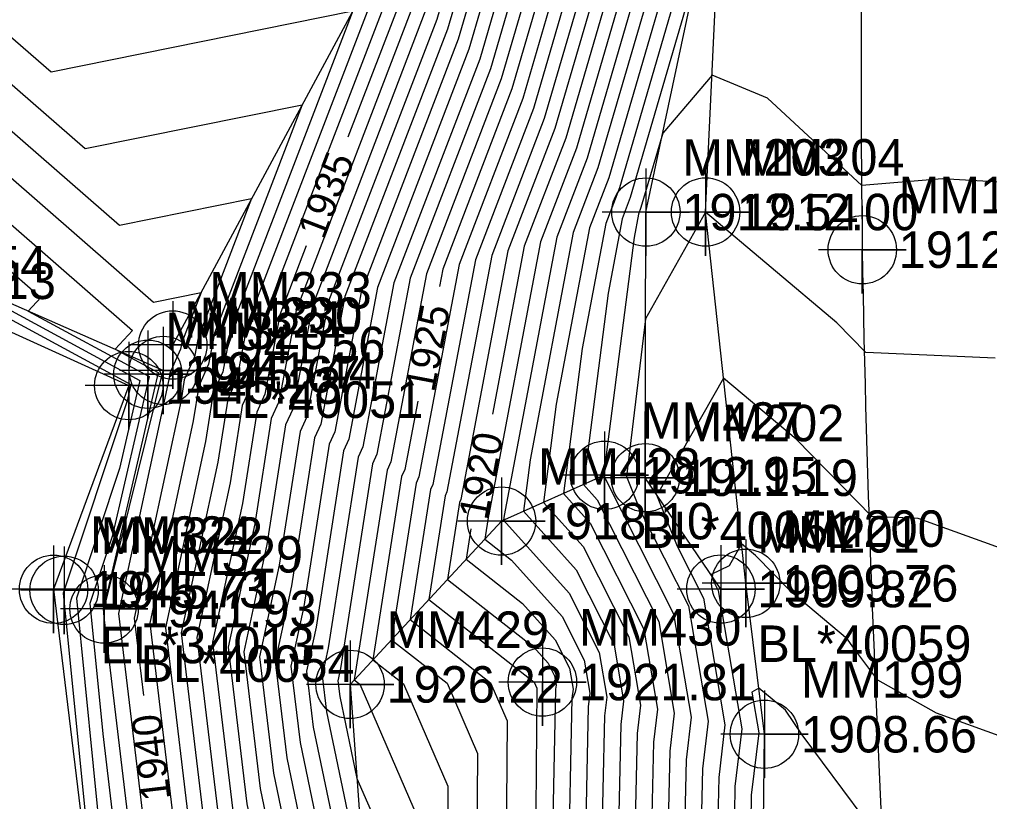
# Model space of a CAD drawing. Extents: x 1004378 to 1005103, y 553854 to 554288.
# Drawn here: x 1004943.2 to 1005009.8, y 554065.8 to 554119.4 of the extents above; entities that cross this region are included whole.
import ezdxf

# ---------------------------------------------------------------- set-up
doc = ezdxf.new("R2010")
doc.units = 0
for name, color, linetype in [('DTM Contours Major', 7, 'Continuous'), ('DTM Contours Major Text', 7, 'Continuous'), ('DTM Contours Minor', 7, 'Continuous'), ('Exist Building Cogo Elevation', 7, 'Continuous'), ('Exist Building Cogo Number', 7, 'Continuous'), ('Exist Building Cogo Point CELL', 7, 'Continuous'), ('Exist DTM Breakline', 7, 'Continuous'), ('Exist DTM Breakline Cogo Comment', 7, 'Continuous'), ('Exist DTM Breakline Cogo Elevation', 7, 'Continuous'), ('Exist DTM Breakline Cogo Number', 7, 'Continuous'), ('Exist DTM Breakline Cogo Point CELL', 7, 'Continuous'), ('Exist DTM Regular Point CELL', 7, 'Continuous'), ('Exist DTM Regular Point Cogo Elevation', 7, 'Continuous'), ('Exist DTM Regular Point Cogo Number', 7, 'Continuous'), ('Exist Roads EOP', 7, 'Continuous'), ('Exist Roads EOP Cogo Elevation', 7, 'Continuous'), ('Exist Roads EOP Cogo Number', 7, 'Continuous'), ('Exist Roads EOP Cogo Point CELL', 7, 'Continuous')]:
    doc.layers.add(name, color=color, linetype=linetype)

msp = doc.modelspace()

# ---------------------------------------------------------------- linework, layer by layer
at = {"layer": 'DTM Contours Major'}
for points in [[(1004988.055, 554197.353), (1004983.519, 554189.087), (1004981.07, 554183.147), (1004980.472, 554180.378), (1004981.231, 554169.159), (1004982.126, 554161.833), (1004982.368, 554159.624), (1004982.603, 554156.477), (1004979.182, 554142.834), (1004980.705, 554127.374), (1004976.99, 554114.65), (1004972.242, 554102.28), (1004972.017, 554101.096)], [(1004997.264, 554188.393), (1004994.509, 554183.373), (1004992.338, 554178.108), (1004990.326, 554169.606), (1004989.594, 554168.865), (1004990.186, 554164.023), (1004990.595, 554160.288), (1004990.667, 554159.321), (1004985.088, 554137.073), (1004985.877, 554129.065), (1004980.677, 554111.255), (1004977.834, 554103.85), (1004975.652, 554092.328)], [(1004974.291, 554156.941), (1004974.539, 554153.633), (1004973.275, 554148.595), (1004975.533, 554125.683), (1004973.303, 554118.045), (1004966.649, 554100.709), (1004964.833, 554091.127), (1004964.446, 554090.268), (1004962.705, 554079.148), (1004961.826, 554075.049), (1004962.449, 554069.829), (1004964.566, 554059.674), (1004964.614, 554059.515)], [(1004919.499, 554152.916), (1004917.744, 554143.914), (1004919.151, 554146.169), (1004918.574, 554141.908), (1004920.21, 554140.992), (1004926.611, 554134.921), (1004928.068, 554135.961), (1004934.459, 554132.981), (1004936.344, 554131.771), (1004937.836, 554132.01), (1004938.33, 554131.579), (1004939.667, 554131.849), (1004957.042, 554136.349), (1004968.89, 554138.926), (1004970.361, 554123.992), (1004969.616, 554121.44), (1004965.738, 554111.337)], [(1004915.782, 554139.515), (1004913.904, 554129.888), (1004921.295, 554123.861), (1004927.208, 554119.035), (1004933.185, 554119.992), (1004950.058, 554105.284), (1004959.128, 554107.116), (1004955.463, 554097.569), (1004955.218, 554096.276), (1004954.505, 554094.696), (1004954.285, 554093.293), (1004951.079, 554078.342), (1004951.712, 554073.035)], [(1005000.387, 554132.231), (1004993.714, 554134.749), (1004991.768, 554134.399), (1004990.994, 554131.312), (1004991.049, 554130.756), (1004984.364, 554107.86), (1004983.427, 554105.42), (1004981.8, 554096.829), (1004980.532, 554086.898), (1004982.359, 554084.869), (1004986.035, 554077.591), (1004986.969, 554072.114), (1004986.697, 554069.843), (1004986.544, 554062.802), (1004985.079, 554049.563), (1004984.328, 554046.826)], [(1004912.064, 554126.115), (1004911.158, 554121.47), (1004914.724, 554118.563), (1004927.833, 554107.862), (1004928.535, 554107.974), (1004932.097, 554104.869), (1004931.879, 554104.636), (1004950.839, 554094.361), (1004950.581, 554093.249), (1004946.204, 554080.072), (1004948.75, 554054.444), (1004948.799, 554054.036), (1004948.807, 554053.997), (1004948.82, 554053.955), (1004947.217, 554049.061)], [(1004962.871, 554103.868), (1004961.056, 554099.139), (1004960.026, 554093.701), (1004959.475, 554092.482), (1004958.495, 554086.221), (1004956.453, 554076.695), (1004957.899, 554064.565), (1004959.313, 554057.782), (1004961.493, 554050.599), (1004960.632, 554047.97), (1004960.758, 554033.678), (1004963.076, 554011.188), (1004962.949, 554005.526)], [(1004970.528, 554093.236), (1004969.641, 554088.552), (1004969.416, 554088.055), (1004967.45, 554075.492), (1004969.542, 554073.85), (1004972.596, 554066.826), (1004972.547, 554060.122), (1004971.354, 554054.113), (1004973.706, 554047.918), (1004974.042, 554047.122), (1004974.026, 554046.818), (1004973.213, 554010.493), (1004972.706, 553999.94), (1004972.315, 553996.671), (1004972.236, 553995.839)], [(1004974.172, 554084.471), (1004973.846, 554082.386), (1004977.708, 554079.356), (1004979.951, 554076.865), (1004980.929, 554074.931), (1004981.177, 554073.474), (1004981.105, 554072.871), (1004980.838, 554060.621), (1004980.413, 554056.78), (1004977.827, 554047.365), (1004979.146, 554044.236), (1004978.97, 554040.918), (1004978.353, 554013.324), (1004977.634, 553998.359), (1004977.079, 553993.724), (1004976.557, 553988.222)], [(1005051.433, 554076.836), (1005050.379, 554076.997), (1005049.638, 554077.419), (1005048.654, 554073.906), (1005043.562, 554064.845), (1005040.05, 554064.129), (1005027.148, 554065.55), (1005021.967, 554066.02), (1005015.22, 554068.538), (1005006.107, 554071.836), (1005002.083, 554074.095), (1005000.368, 554076.389), (1005000.016, 554076.907), (1004996.136, 554080.152), (1004993.696, 554082.636), (1004992.74, 554083.442), (1004991.884, 554081.943), (1004990.65, 554081.337), (1004990.87, 554080.789), (1004991.142, 554080.251), (1004992.761, 554070.753), (1004992.29, 554066.815), (1004992.25, 554064.983), (1004991.398, 554057.275)]]:
    msp.add_lwpolyline(points, dxfattribs=at)
at = {"layer": 'DTM Contours Minor'}
for points in [[(1004988.98, 554130.079), (1004982.889, 554109.218), (1004981.19, 554104.792), (1004978.237, 554089.207), (1004977.787, 554085.675), (1004981.396, 554081.667), (1004983.993, 554076.527), (1004984.652, 554072.658), (1004984.46, 554071.054), (1004984.262, 554061.93), (1004983.213, 554052.45), (1004981.163, 554044.985), (1004982.208, 554042.504), (1004981.937, 554037.378), (1004981.437, 554015.023)], [(1004990.014, 554130.417), (1004983.627, 554108.539), (1004982.309, 554105.106), (1004980.019, 554093.018), (1004979.159, 554086.286), (1004981.877, 554083.268), (1004985.014, 554077.059), (1004985.811, 554072.386), (1004985.579, 554070.449), (1004985.403, 554062.366), (1004984.146, 554051.006), (1004982.275, 554044.191), (1004983.229, 554041.926), (1004982.926, 554036.198), (1004982.465, 554015.589)], [(1004986.911, 554129.403), (1004981.414, 554110.576), (1004978.953, 554104.164), (1004975.41, 554085.463), (1004975.381, 554085.398), (1004975.125, 554083.765), (1004976.951, 554082.333), (1004980.433, 554078.466), (1004981.95, 554075.463), (1004982.335, 554073.202), (1004982.223, 554072.265), (1004981.979, 554061.057), (1004981.346, 554055.337), (1004978.939, 554046.571), (1004980.166, 554043.658), (1004979.959, 554039.738), (1004979.381, 554013.891)], [(1004987.946, 554129.741), (1004982.152, 554109.897), (1004980.072, 554104.478), (1004976.456, 554085.395), (1004976.414, 554085.064), (1004980.914, 554080.067), (1004982.971, 554075.995), (1004983.494, 554072.93), (1004983.342, 554071.66), (1004983.12, 554061.493), (1004982.279, 554053.893), (1004980.051, 554045.778), (1004981.187, 554043.081), (1004980.948, 554038.558), (1004980.409, 554014.457)], [(1004983.808, 554128.388), (1004979.202, 554112.613), (1004975.597, 554103.222), (1004972.525, 554087.008), (1004972.399, 554086.726), (1004971.288, 554079.628), (1004978.513, 554073.96), (1004978.694, 554073.543), (1004978.613, 554062.384), (1004978.555, 554059.749), (1004978.546, 554059.667), (1004975.604, 554048.951), (1004977.104, 554045.39), (1004976.992, 554043.278), (1004976.297, 554012.192)], [(1004984.843, 554128.727), (1004979.94, 554111.934), (1004976.716, 554103.536), (1004973.487, 554086.493), (1004973.393, 554086.284), (1004972.567, 554081.007), (1004978.466, 554076.38), (1004979.47, 554075.265), (1004979.907, 554074.399), (1004980.018, 554073.747), (1004979.986, 554073.476), (1004979.696, 554060.185), (1004979.479, 554058.224), (1004976.716, 554048.158), (1004978.125, 554044.813), (1004977.981, 554042.098), (1004977.325, 554012.758)], [(1004981.739, 554127.712), (1004977.727, 554113.971), (1004973.36, 554102.594), (1004970.602, 554088.037), (1004970.41, 554087.612), (1004968.729, 554076.871), (1004972.533, 554073.887), (1004974.629, 554069.065), (1004974.562, 554059.989), (1004972.947, 554051.855), (1004974.061, 554048.923), (1004975.063, 554046.545), (1004975.015, 554045.638), (1004974.241, 554011.059)], [(1004982.774, 554128.05), (1004978.465, 554113.292), (1004974.479, 554102.908), (1004971.564, 554087.523), (1004971.404, 554087.169), (1004970.008, 554078.249), (1004975.523, 554073.924), (1004976.661, 554071.304), (1004976.578, 554059.857), (1004974.774, 554050.773), (1004974.492, 554049.745), (1004976.083, 554045.967), (1004976.003, 554044.458), (1004975.269, 554011.625)], [(1004979.671, 554127.036), (1004976.253, 554115.329), (1004971.123, 554101.966), (1004968.679, 554089.067), (1004968.422, 554088.497), (1004966.171, 554074.113), (1004966.552, 554073.814), (1004970.563, 554064.587), (1004970.531, 554060.254), (1004969.76, 554056.371), (1004972.101, 554050.208), (1004972.899, 554047.579), (1004972.854, 554047.442), (1004972.86, 554046.695), (1004972.981, 554045.52), (1004972.185, 554009.926)], [(1004977.602, 554126.359), (1004974.778, 554116.687), (1004968.886, 554101.338), (1004966.756, 554090.097), (1004966.434, 554089.383), (1004964.389, 554076.319), (1004963.976, 554074.391), (1004964.268, 554071.934), (1004966.667, 554060.431), (1004970.364, 554048.25), (1004970.138, 554047.559), (1004970.171, 554043.802), (1004970.78, 554037.89), (1004970.129, 554008.794)], [(1004978.636, 554126.697), (1004975.515, 554116.008), (1004970.004, 554101.652), (1004967.718, 554089.582), (1004967.428, 554088.94), (1004965.231, 554074.905), (1004965.05, 554074.061), (1004965.178, 554072.987), (1004966.353, 554067.357), (1004968.53, 554062.348), (1004968.516, 554060.387), (1004968.167, 554058.63), (1004969.226, 554055.84), (1004971.631, 554047.915), (1004971.496, 554047.501), (1004971.516, 554045.249), (1004971.881, 554041.705), (1004971.157, 554009.36)], [(1005041.535, 554126.294), (1005027.186, 554113.002), (1005025.646, 554112.306), (1005019.626, 554109.515), (1005013.669, 554108.071), (1005006.504, 554108.468), (1005001.004, 554108.005), (1004994.526, 554114.001), (1004990.716, 554115.591), (1004987.329, 554111.605), (1004985.839, 554106.502), (1004985.665, 554106.048), (1004985.362, 554104.451), (1004983.277, 554088.12), (1004983.322, 554088.07), (1004988.078, 554078.655), (1004989.286, 554071.569), (1004988.935, 554068.632), (1004988.827, 554063.674), (1004986.946, 554046.675), (1004985.61, 554041.811), (1004986.291, 554040.195), (1004985.892, 554032.658), (1004985.548, 554017.288)], [(1004976.568, 554126.021), (1004974.041, 554117.366), (1004967.767, 554101.024), (1004965.795, 554090.612), (1004965.44, 554089.826), (1004963.547, 554077.734), (1004962.901, 554074.72), (1004963.358, 554070.882), (1004965.617, 554060.053), (1004969.097, 554048.586), (1004968.78, 554047.618), (1004968.826, 554042.356), (1004969.679, 554034.076), (1004969.101, 554008.227)], [(1004935.046, 554124.799), (1004945.367, 554115.802), (1004966.063, 554119.983), (1004957.7, 554098.197), (1004957.141, 554095.246), (1004956.493, 554093.81), (1004955.969, 554090.464), (1004953.229, 554077.683), (1004955.169, 554061.406), (1004956.161, 554056.646), (1004957.691, 554051.606), (1004956.558, 554048.146), (1004956.724, 554029.339)], [(1004973.465, 554125.006), (1004971.828, 554119.403), (1004964.412, 554100.081), (1004962.91, 554092.157), (1004962.458, 554091.154), (1004961.021, 554081.977), (1004959.677, 554075.708), (1004960.629, 554067.723), (1004962.465, 554058.917), (1004965.295, 554049.592), (1004964.706, 554047.794), (1004964.792, 554038.017), (1004966.378, 554022.632)], [(1004974.499, 554125.345), (1004972.566, 554118.724), (1004965.53, 554100.395), (1004963.872, 554091.642), (1004963.452, 554090.711), (1004961.863, 554080.563), (1004960.752, 554075.378), (1004961.539, 554068.776), (1004963.515, 554059.296), (1004966.562, 554049.257), (1004966.064, 554047.735), (1004966.137, 554039.463), (1004967.478, 554026.447)], [(1004989.854, 554123.457), (1004985.101, 554107.181), (1004984.546, 554105.734), (1004983.581, 554100.64), (1004981.905, 554087.509), (1004982.841, 554086.469), (1004987.056, 554078.123), (1004988.127, 554071.842), (1004987.816, 554069.238), (1004987.685, 554063.238), (1004986.012, 554048.119), (1004984.498, 554042.605), (1004985.27, 554040.772), (1004984.903, 554033.838), (1004984.52, 554016.722)], [(1004919.981, 554122.802), (1004927.333, 554116.8), (1004932.255, 554117.588), (1004952.404, 554100.025), (1004955.66, 554100.683), (1004954.344, 554097.255), (1004954.256, 554096.791), (1004953.511, 554095.139), (1004953.443, 554094.708), (1004950.005, 554078.671), (1004952.439, 554058.248), (1004953.009, 554055.511), (1004953.889, 554052.612), (1004952.484, 554048.322), (1004952.69, 554025)], [(1004968.142, 554122.798), (1004958.819, 554098.511), (1004958.102, 554094.731), (1004957.487, 554093.368), (1004956.811, 554089.05), (1004954.303, 554077.354), (1004956.079, 554062.459), (1004957.212, 554057.025), (1004958.958, 554051.27), (1004957.916, 554048.088), (1004958.069, 554030.785)], [(1004934.115, 554122.395), (1004947.713, 554110.543), (1004962.595, 554113.55), (1004956.581, 554097.883), (1004956.179, 554095.761), (1004955.499, 554094.253), (1004955.127, 554091.879), (1004952.154, 554078.013), (1004954.259, 554060.353), (1004955.111, 554056.268), (1004956.424, 554051.941), (1004955.2, 554048.205), (1004955.379, 554027.893)], [(1004968.879, 554122.119), (1004959.937, 554098.825), (1004959.064, 554094.216), (1004958.481, 554092.925), (1004957.653, 554087.635), (1004955.378, 554077.025), (1004956.989, 554063.512), (1004958.262, 554057.403), (1004960.226, 554050.935), (1004959.274, 554048.029), (1004959.413, 554032.232), (1004961.975, 554007.374)], [(1004918.667, 554121.742), (1004927.458, 554114.566), (1004931.325, 554115.185), (1004950.953, 554098.075), (1004949.754, 554096.79), (1004952.721, 554095.183), (1004949.04, 554079.301), (1004948.941, 554079.002), (1004948.999, 554078.42), (1004951.529, 554057.195), (1004951.959, 554055.132), (1004952.622, 554052.948), (1004951.126, 554048.381), (1004951.345, 554023.554)], [(1004970.354, 554120.761), (1004962.174, 554099.453), (1004960.987, 554093.186), (1004960.469, 554092.039), (1004959.337, 554084.806), (1004957.527, 554076.366), (1004958.809, 554065.617), (1004960.364, 554058.16), (1004962.76, 554050.264), (1004961.99, 554047.911), (1004962.103, 554035.124), (1004964.176, 554015.003)], [(1004917.352, 554120.683), (1004927.583, 554112.331), (1004930.395, 554112.781), (1004944.668, 554100.34), (1004943.796, 554099.406), (1004952.093, 554094.909), (1004949.554, 554083.951), (1004948.029, 554079.359), (1004948.916, 554070.428), (1004950.619, 554056.142), (1004950.908, 554054.754), (1004951.354, 554053.283), (1004949.768, 554048.44), (1004950.001, 554022.107)], [(1004971.091, 554120.082), (1004963.293, 554099.767), (1004961.949, 554092.671), (1004961.463, 554091.597), (1004960.179, 554083.392), (1004958.602, 554076.037), (1004959.719, 554066.67), (1004961.414, 554058.539), (1004964.027, 554049.928), (1004963.348, 554047.853), (1004963.448, 554036.571), (1004965.277, 554018.817)], [(1004916.038, 554119.623), (1004927.708, 554110.097), (1004929.465, 554110.378), (1004938.382, 554102.604), (1004937.837, 554102.021), (1004951.466, 554094.635), (1004950.068, 554088.6), (1004947.116, 554079.715), (1004948.833, 554062.436), (1004949.709, 554055.089), (1004949.858, 554054.375), (1004950.087, 554053.619), (1004948.41, 554048.498), (1004948.656, 554020.661)], [(1005010.132, 554096.182), (1005001.278, 554096.56), (1004999.274, 554098.601), (1004990.276, 554106.187), (1004990.27, 554106.177), (1004986.161, 554098.879), (1004984.854, 554088.057), (1004985.769, 554085.78), (1004989.099, 554079.187), (1004990.444, 554071.297), (1004990.053, 554068.027), (1004989.968, 554064.111), (1004987.879, 554045.232), (1004986.722, 554041.018), (1004987.312, 554039.617), (1004986.881, 554031.478), (1004986.576, 554017.855)], [(1005014.682, 554081.634), (1005004.85, 554085.192), (1005001.681, 554085.328), (1004996.485, 554090.618), (1004991.508, 554094.815), (1004987.057, 554087.013), (1004986.86, 554086.916), (1004988.319, 554083.285), (1004990.12, 554079.719), (1004991.603, 554071.025), (1004991.172, 554067.421), (1004991.109, 554064.547), (1004988.812, 554043.788), (1004987.834, 554040.225), (1004988.333, 554039.04), (1004987.87, 554030.298)], [(1005050.437, 554057.486), (1005048.879, 554054.931), (1005048.518, 554054.142), (1005043.793, 554047.065), (1005040.855, 554048.876), (1005027.803, 554050.713), (1005026.234, 554051.882), (1005016.31, 554055.236), (1005015.759, 554055.441), (1005015.604, 554055.497), (1005002.486, 554062.863), (1004996.894, 554070.341), (1004995.745, 554072.029), (1004993.918, 554073.557), (1004993.443, 554073.279), (1004993.92, 554070.481), (1004993.409, 554066.21), (1004993.392, 554065.419), (1004990.679, 554040.901), (1004990.057, 554038.638), (1004990.374, 554037.886), (1004989.848, 554027.938)]]:
    msp.add_lwpolyline(points, dxfattribs=at)
at = {"layer": 'Exist Building Cogo Point CELL'}
for points in [[(1004952.008, 554098.071), (1004952.008, 554092.071), (1004952.008, 554095.071), (1004955.008, 554095.071), (1004949.008, 554095.071)], [(1004946.261, 554083.257), (1004946.261, 554077.257), (1004946.261, 554080.257), (1004949.261, 554080.257), (1004943.261, 554080.257)]]:
    msp.add_lwpolyline(points, dxfattribs=at)
for centre in [(1004952.008, 554095.071), (1004946.261, 554080.257)]:
    msp.add_circle(centre, 2.344, dxfattribs=at)
at = {"layer": 'Exist DTM Breakline'}
for points in [[(1004999.282, 554239.926), (1004986.87, 554220.91), (1004973.315, 554188.37), (1004969.818, 554151.968), (1004967.766, 554123.144), (1004953.718, 554097.079)], [(1004987.71, 553883.194), (1004993.763, 553908.865), (1004995.956, 553952.192), (1004996.06, 553992.449), (1004993.928, 554035.876), (1004994.309, 554070.389), (1004993.033, 554080.737), (1004990.275, 554106.198), (1004991.435, 554130.882), (1004994.664, 554165.005), (1004997.714, 554181.706), (1005005.106, 554206.988)], [(1004991.323, 554080.346), (1004986.139, 554087.977), (1004986.175, 554106.192), (1004991.435, 554130.882)], [(1004908.599, 554113.626), (1004928.542, 554104.358), (1004950.697, 554094.299), (1004945.541, 554080.331), (1004948.745, 554053.974), (1004946.395, 554048.586), (1004946.774, 554014.511), (1004946.946, 553994.845), (1004942.426, 553964.624), (1004933.56, 553959.38), (1004919.92, 553960.138), (1004910.869, 553961.543), (1004894.885, 553951.978), (1004894.101, 553924.52), (1004896.848, 553886.739), (1004896.026, 553883.694)], [(1004949.005, 554078.977), (1004953.07, 554095.335), (1004927.916, 554106.376)], [(1004983.346, 554088.15), (1004976.272, 554085.001), (1004965.886, 554073.806), (1004966.849, 554060.497), (1004974.38, 554049.825)]]:
    msp.add_lwpolyline(points, dxfattribs=at)
at = {"layer": 'Exist DTM Breakline Cogo Point CELL'}
for points in [[(1004986.175, 554109.192), (1004986.175, 554103.192), (1004986.175, 554106.192), (1004989.175, 554106.192), (1004983.175, 554106.192)], [(1004990.275, 554109.198), (1004990.275, 554103.198), (1004990.275, 554106.198), (1004993.275, 554106.198), (1004987.275, 554106.198)], [(1004953.718, 554100.079), (1004953.718, 554094.079), (1004953.718, 554097.079), (1004956.718, 554097.079), (1004950.718, 554097.079)], [(1004953.07, 554098.335), (1004953.07, 554092.335), (1004953.07, 554095.335), (1004956.07, 554095.335), (1004950.07, 554095.335)], [(1004950.697, 554097.299), (1004950.697, 554091.299), (1004950.697, 554094.299), (1004953.697, 554094.299), (1004947.697, 554094.299)], [(1004983.346, 554091.15), (1004983.346, 554085.15), (1004983.346, 554088.15), (1004986.346, 554088.15), (1004980.346, 554088.15)], [(1004986.139, 554090.977), (1004986.139, 554084.977), (1004986.139, 554087.977), (1004989.139, 554087.977), (1004983.139, 554087.977)], [(1004976.272, 554088.001), (1004976.272, 554082.001), (1004976.272, 554085.001), (1004979.272, 554085.001), (1004973.272, 554085.001)], [(1004993.033, 554083.737), (1004993.033, 554077.737), (1004993.033, 554080.737), (1004996.033, 554080.737), (1004990.033, 554080.737)], [(1004945.541, 554083.331), (1004945.541, 554077.331), (1004945.541, 554080.331), (1004948.541, 554080.331), (1004942.541, 554080.331)], [(1004991.323, 554083.346), (1004991.323, 554077.346), (1004991.323, 554080.346), (1004994.323, 554080.346), (1004988.323, 554080.346)], [(1004949.005, 554081.977), (1004949.005, 554075.977), (1004949.005, 554078.977), (1004952.005, 554078.977), (1004946.005, 554078.977)], [(1004965.886, 554076.806), (1004965.886, 554070.806), (1004965.886, 554073.806), (1004968.886, 554073.806), (1004962.886, 554073.806)], [(1004994.309, 554073.389), (1004994.309, 554067.389), (1004994.309, 554070.389), (1004997.309, 554070.389), (1004991.309, 554070.389)]]:
    msp.add_lwpolyline(points, dxfattribs=at)
for centre in [(1004986.175, 554106.192), (1004990.275, 554106.198), (1004953.718, 554097.079), (1004953.07, 554095.335), (1004950.697, 554094.299), (1004983.346, 554088.15), (1004986.139, 554087.977), (1004976.272, 554085.001), (1004993.033, 554080.737), (1004945.541, 554080.331), (1004991.323, 554080.346), (1004949.005, 554078.977), (1004965.886, 554073.806), (1004994.309, 554070.389)]:
    msp.add_circle(centre, 2.344, dxfattribs=at)
at = {"layer": 'Exist DTM Regular Point CELL'}
msp.add_lwpolyline([(1004979.079, 554076.967), (1004979.079, 554070.967), (1004979.079, 554073.967), (1004982.079, 554073.967), (1004976.079, 554073.967)], dxfattribs=at)
msp.add_circle((1004979.079, 554073.967), 2.344, dxfattribs=at)
at = {"layer": 'Exist Roads EOP'}
msp.add_spline([(1005026.381, 554243.671), (1005017.049, 554225.785), (1005004.478, 554185.698), (1005001.445, 554147.868), (1005001.025, 554103.612), (1005002.785, 554054.517)], degree=3, dxfattribs=at)
at = {"layer": 'Exist Roads EOP Cogo Point CELL'}
msp.add_lwpolyline([(1005001.025, 554106.612), (1005001.025, 554100.612), (1005001.025, 554103.612), (1005004.025, 554103.612), (1004998.025, 554103.612)], dxfattribs=at)
msp.add_circle((1005001.025, 554103.612), 2.344, dxfattribs=at)

# ---------------------------------------------------------------- texts
at = {"layer": 'DTM Contours Major Text'}
for s, rotation, p in [('1935', 68.99986, (1004964.084, 554104.238)), ('1925', 79.27196, (1004971.65, 554093.785)), ('1920', 79.33745, (1004975.288, 554085.017)), ('1940', 96.79687, (1004953.563, 554065.952))]:
    msp.add_text(s, height=2, rotation=rotation, dxfattribs=at).set_placement(p)
at = {"layer": 'Exist Building Cogo Elevation'}
for s, p in [('BL*34013', (1004931.015, 554100.229)), ('1945.67', (1004954.508, 554093.821)), ('1945.71', (1004948.761, 554079.007)), ('EL*34013', (1004948.761, 554075.257))]:
    msp.add_text(s, height=2.5, dxfattribs=at).set_placement(p)
at = {"layer": 'Exist Building Cogo Number'}
for s, p in [('MM321', (1004954.508, 554097.571)), ('MM322', (1004948.761, 554082.757))]:
    msp.add_text(s, height=2.5, dxfattribs=at).set_placement(p)
at = {"layer": 'Exist DTM Breakline Cogo Comment'}
for s, p in [('EL*40054', (1004930.416, 554101.376)), ('EL*40051', (1004956.218, 554092.079)), ('BL*40051', (1004985.846, 554083.15)), ('BL*40059', (1004993.823, 554075.346)), ('BL*40054', (1004951.505, 554073.977))]:
    msp.add_text(s, height=2.5, dxfattribs=at).set_placement(p)
at = {"layer": 'Exist DTM Breakline Cogo Elevation'}
for s, p in [('1912.54', (1004988.675, 554104.942)), ('1912.00', (1004992.775, 554104.948)), ('1941.56', (1004956.218, 554095.829)), ('1941.44', (1004955.57, 554094.085)), ('1945.23', (1004953.197, 554093.049)), ('1912.95', (1004985.846, 554086.9)), ('1911.19', (1004988.639, 554086.727)), ('1918.10', (1004978.772, 554083.751)), ('1945.73', (1004948.041, 554079.081)), ('1909.82', (1004993.823, 554079.096)), ('1909.76', (1004995.533, 554079.487)), ('1941.93', (1004951.505, 554077.727)), ('1926.22', (1004968.386, 554072.556)), ('1908.66', (1004996.809, 554069.139))]:
    msp.add_text(s, height=2.5, dxfattribs=at).set_placement(p)
at = {"layer": 'Exist DTM Breakline Cogo Number'}
for s, p in [('MM203', (1004988.675, 554108.692)), ('MM204', (1004992.775, 554108.698)), ('MM333', (1004956.218, 554099.579)), ('MM330', (1004955.57, 554097.835)), ('MM323', (1004953.197, 554096.799)), ('MM427', (1004985.846, 554090.65)), ('MM202', (1004988.639, 554090.477)), ('MM428', (1004978.772, 554087.501)), ('MM200', (1004995.533, 554083.237)), ('MM324', (1004948.041, 554082.831)), ('MM201', (1004993.823, 554082.846)), ('MM329', (1004951.505, 554081.477)), ('MM429', (1004968.386, 554076.306)), ('MM199', (1004996.809, 554072.889))]:
    msp.add_text(s, height=2.5, dxfattribs=at).set_placement(p)
at = {"layer": 'Exist DTM Regular Point Cogo Elevation'}
msp.add_text('1921.81', height=2.5, dxfattribs=at).set_placement((1004981.579, 554072.717))
at = {"layer": 'Exist DTM Regular Point Cogo Number'}
msp.add_text('MM430', height=2.5, dxfattribs=at).set_placement((1004981.579, 554076.467))
at = {"layer": 'Exist Roads EOP Cogo Elevation'}
msp.add_text('1912.63', height=2.5, dxfattribs=at).set_placement((1005003.525, 554102.362))
at = {"layer": 'Exist Roads EOP Cogo Number'}
msp.add_text('MM138', height=2.5, dxfattribs=at).set_placement((1005003.525, 554106.112))

doc.saveas('drawing.dxf')
